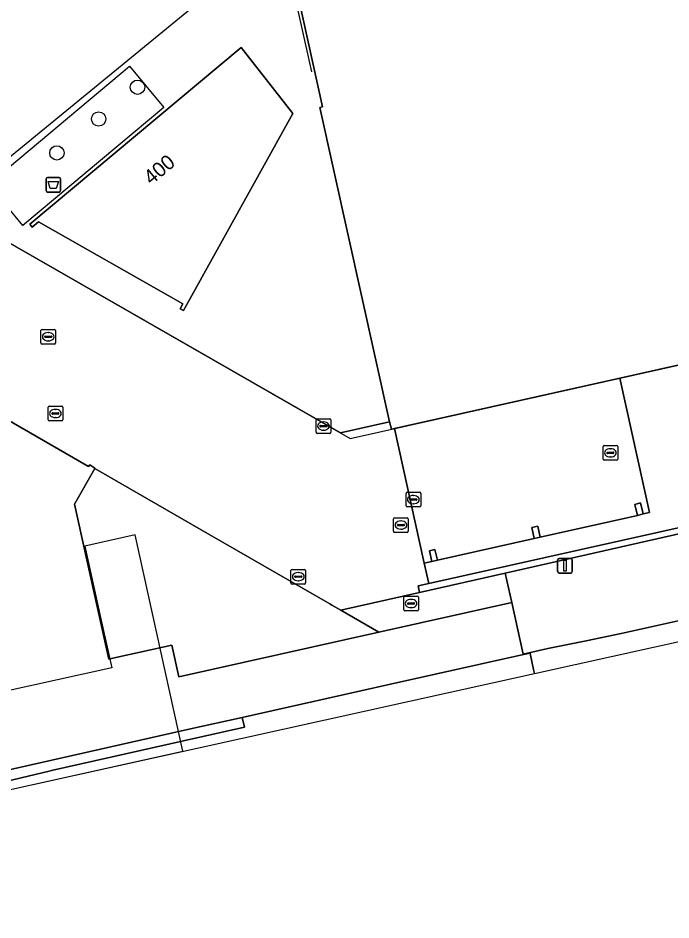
# Model space of a CAD drawing. Extents: x 160806 to 161707, y 383696 to 384148.
# Drawn here: x 161433.9 to 161478.4, y 383803.8 to 383865.4 of the extents above; entities that cross this region are included whole.
import ezdxf

# ---------------------------------------------------------------- set-up
doc = ezdxf.new("R2010")
doc.units = 0
for name, color, linetype in [('IMGEO_Afvalbak', 7, 'Continuous'), ('IMGEO_Boom', 7, 'Continuous'), ('IMGEO_Erf', 7, 'Continuous'), ('IMGEO_Groenvoorziening', 7, 'Continuous'), ('IMGEO_Hek', 7, 'Continuous'), ('IMGEO_Kolk', 7, 'Continuous'), ('IMGEO_Lichtmast', 7, 'Continuous'), ('IMGEO_Lijnafwatering', 7, 'Continuous'), ('IMGEO_Pand', 7, 'Continuous'), ('IMGEO_Pand_nummerreeks', 7, 'Continuous'), ('IMGEO_Pand_overbouw', 7, 'Continuous'), ('IMGEO_Pand_vergunning_verleend', 7, 'Continuous'), ('IMGEO_Rijbaan_lokaal_gesloten', 7, 'Continuous'), ('IMGEO_Rijbaan_lokaal_open', 7, 'Continuous'), ('IMGEO_Rioolput', 7, 'Continuous'), ('IMGEO_Spoorbaan_halfverhard', 7, 'Continuous'), ('IMGEO_Terreindeel_gesloten', 7, 'Continuous'), ('IMGEO_Verkeerseiland_open', 7, 'Continuous'), ('IMGEO_Voetgangersgebied_open', 7, 'Continuous'), ('IMGEO_Voetpad_open', 7, 'Continuous')]:
    doc.layers.add(name, color=color, linetype=linetype)

msp = doc.modelspace()

# ---------------------------------------------------------------- linework, layer by layer
at = {"layer": 'IMGEO_Afvalbak'}
for p, q in [((161435.802, 383853.602), (161435.802, 383854.402)), ((161435.802, 383854.402), (161435.802, 383853.602)), ((161435.902, 383854.502), (161436.692, 383854.502)), ((161436.692, 383854.502), (161435.902, 383854.502)), ((161436.792, 383854.402), (161436.792, 383853.602)), ((161436.792, 383853.602), (161436.792, 383854.402)), ((161436.692, 383853.502), (161435.902, 383853.502)), ((161435.902, 383853.502), (161436.692, 383853.502))]:
    msp.add_line(p, q, dxfattribs=at)
msp.add_lwpolyline([(161435.945, 383854.216), (161436.649, 383854.216), (161436.5, 383853.746), (161436.094, 383853.746), (161435.945, 383854.216)], dxfattribs=at)
for centre, start, end in [((161435.902, 383854.402), 90, 180), ((161435.902, 383854.402), 90, 180), ((161436.692, 383854.402), 0, 90), ((161436.692, 383854.402), 360, 90), ((161435.902, 383853.602), 180, 270), ((161435.902, 383853.602), 180, 270), ((161436.692, 383853.602), 270, 0), ((161436.692, 383853.602), 270, 0)]:
    msp.add_arc(centre, 0.1, start, end, dxfattribs=at)
at = {"layer": 'IMGEO_Boom'}
for centre in [(161442.039, 383860.652), (161439.388, 383858.484), (161436.538, 383856.171)]:
    msp.add_circle(centre, 0.489, dxfattribs=at)
at = {"layer": 'IMGEO_Erf'}
msp.add_lwpolyline([(161439.133, 383834.644), (161437.743, 383832.2), (161440.079, 383821.637), (161440.151, 383821.653), (161444.389, 383822.588), (161444.86, 383820.431), (161458.497, 383823.475), (161455.916, 383824.962), (161455.299, 383825.318), (161455.145, 383825.407), (161446.976, 383830.114)], close=True, dxfattribs=at)
at = {"layer": 'IMGEO_Groenvoorziening'}
msp.add_lwpolyline([(161573.981, 383851.379), (161498.641, 383834.626), (161467.119, 383827.496), (161467.565, 383825.499), (161468.352, 383821.972), (161470.021, 383822.345), (161472.634, 383822.879), (161475.023, 383823.371), (161479.934, 383824.467), (161509.272, 383830.942), (161514.217, 383832.035), (161521.635, 383833.723), (161580.201, 383846.689)], dxfattribs=at)
at = {"layer": 'IMGEO_Hek'}
for points in [[(161468.352, 383821.972), (161470.021, 383822.345), (161472.634, 383822.879), (161475.023, 383823.371), (161479.934, 383824.467), (161509.272, 383830.942), (161514.217, 383832.035), (161521.635, 383833.723), (161580.201, 383846.689), (161582.51, 383847.687), (161585.012, 383847.75), (161614.342, 383854.325), (161641.301, 383860.274), (161651.06, 383862.411), (161662.497, 383864.892), (161670.593, 383866.669), (161682.93, 383869.376), (161687.731, 383870.454), (161692.46, 383871.911), (161696.167, 383872.737)], [(161439.133, 383834.644), (161446.976, 383830.114), (161455.145, 383825.407)], [(161455.145, 383825.407), (161455.299, 383825.318)], [(161455.299, 383825.318), (161455.916, 383824.962)], [(161455.916, 383824.962), (161458.497, 383823.475)], [(161468.36, 383821.937), (161459.292, 383819.913), (161449.186, 383817.657)], [(161449.186, 383817.657), (161445.655, 383816.869), (161421.996, 383811.526)]]:
    msp.add_lwpolyline(points, dxfattribs=at)
at = {"layer": 'IMGEO_Kolk'}
for p, q in [((161454.221, 383837.106), (161454.221, 383837.958)), ((161454.296, 383838.032), (161455.148, 383838.032)), ((161454.709, 383837.812), (161454.734, 383837.812)), ((161455.222, 383837.958), (161455.222, 383837.106)), ((161454.48, 383837.526), (161454.48, 383837.538)), ((161454.918, 383837.489), (161454.52, 383837.489)), ((161454.523, 383837.575), (161454.921, 383837.575)), ((161454.732, 383837.252), (161454.707, 383837.252)), ((161454.964, 383837.538), (161454.964, 383837.526)), ((161455.148, 383837.032), (161454.296, 383837.032)), ((161452.506, 383826.829), (161452.506, 383827.681)), ((161452.581, 383827.755), (161453.433, 383827.755)), ((161452.808, 383827.298), (161453.206, 383827.298)), ((161452.994, 383827.535), (161453.019, 383827.535)), ((161453.507, 383827.681), (161453.507, 383826.829)), ((161453.433, 383826.755), (161452.581, 383826.755)), ((161452.765, 383827.249), (161452.765, 383827.261)), ((161453.203, 383827.212), (161452.805, 383827.212)), ((161453.017, 383826.975), (161452.992, 383826.975)), ((161453.249, 383827.261), (161453.249, 383827.249))]:
    msp.add_line(p, q, dxfattribs=at)
for points in [[(161454.221, 383837.106), (161454.221, 383837.958)], [(161454.296, 383838.032), (161455.148, 383838.032)], [(161455.222, 383837.958), (161455.222, 383837.106)], [(161455.148, 383837.032), (161454.296, 383837.032)], [(161452.506, 383826.829), (161452.506, 383827.681)], [(161452.581, 383827.755), (161453.433, 383827.755)], [(161453.507, 383827.681), (161453.507, 383826.829)], [(161453.433, 383826.755), (161452.581, 383826.755)]]:
    msp.add_lwpolyline(points, dxfattribs=at)
for centre, radius, start, end in [((161454.298, 383837.956), 0.0765, 91.55205, 178.44795), ((161454.298, 383837.956), 0.0765, 91.55205, 178.44795), ((161455.146, 383837.956), 0.0765, 1.55205, 88.44795), ((161455.146, 383837.956), 0.0765, 1.55205, 88.44795), ((161454.52, 383837.535), 0.0403, 85.87752, 175.75265), ((161454.517, 383837.525), 0.0366, 178.93798, 274.71019), ((161454.921, 383837.532), 0.043, 264.86636, 352.45326), ((161454.925, 383837.537), 0.0386, 1.73085, 96.63898), ((161454.298, 383837.108), 0.0765, 181.55205, 268.44795), ((161454.298, 383837.108), 0.0765, 181.55205, 268.44795), ((161455.146, 383837.108), 0.0765, 271.55205, 358.44795), ((161455.146, 383837.108), 0.0765, 271.55205, 358.44795), ((161452.583, 383827.679), 0.0765, 91.55205, 178.44795), ((161452.583, 383827.679), 0.0765, 91.55205, 178.44795), ((161452.805, 383827.258), 0.0403, 85.87752, 175.75265), ((161453.21, 383827.26), 0.0386, 1.73085, 96.63898), ((161453.431, 383827.679), 0.0765, 1.55205, 88.44795), ((161453.431, 383827.679), 0.0765, 1.55205, 88.44795), ((161452.583, 383826.831), 0.0765, 181.55205, 268.44795), ((161452.583, 383826.831), 0.0765, 181.55205, 268.44795), ((161452.802, 383827.248), 0.0366, 178.93798, 274.71019), ((161453.206, 383827.255), 0.043, 264.86636, 352.45326), ((161453.431, 383826.831), 0.0765, 271.55205, 358.44795), ((161453.431, 383826.831), 0.0765, 271.55205, 358.44795)]:
    msp.add_arc(centre, radius, start, end, dxfattribs=at)
for centre, major_axis, ratio, start_param, end_param in [((161454.708, 383837.532), (-0.387, 0.002), 0.722429, 4.712389, 7.853982), ((161454.733, 383837.532), (-0.39, 0.002), 0.717154, 1.570796, 4.712389), ((161452.993, 383827.255), (-0.387, 0.002), 0.722429, 4.712389, 7.853982), ((161453.018, 383827.255), (-0.39, 0.002), 0.717154, 1.570796, 4.712389)]:
    msp.add_ellipse(centre, major_axis=major_axis, ratio=ratio, start_param=start_param, end_param=end_param, dxfattribs=at)
at = {"layer": 'IMGEO_Lichtmast'}
for p, q in [((161470.693, 383827.601), (161470.693, 383828.401)), ((161470.693, 383828.401), (161470.693, 383827.601)), ((161470.793, 383828.501), (161471.583, 383828.501)), ((161471.583, 383828.501), (161470.793, 383828.501)), ((161471.683, 383828.401), (161471.683, 383827.601)), ((161471.683, 383827.601), (161471.683, 383828.401)), ((161471.583, 383827.501), (161470.793, 383827.501)), ((161470.793, 383827.501), (161471.583, 383827.501))]:
    msp.add_line(p, q, dxfattribs=at)
msp.add_lwpolyline([(161471.113, 383828.376), (161471.263, 383828.376), (161471.263, 383827.626), (161471.113, 383827.626), (161471.113, 383828.376)], dxfattribs=at)
for centre, start, end in [((161470.793, 383828.401), 90, 180), ((161470.793, 383828.401), 90, 180), ((161471.583, 383828.401), 0, 90), ((161471.583, 383828.401), 360, 90), ((161470.793, 383827.601), 180, 270), ((161470.793, 383827.601), 180, 270), ((161471.583, 383827.601), 270, 0), ((161471.583, 383827.601), 270, 0)]:
    msp.add_arc(centre, 0.1, start, end, dxfattribs=at)
at = {"layer": 'IMGEO_Lijnafwatering'}
for points in [[(161451.826, 383870.993), (161453.9, 383861.703)], [(161446.281, 383866.489), (161429.508, 383852.763)]]:
    msp.add_lwpolyline(points, dxfattribs=at)
at = {"layer": 'IMGEO_Pand'}
for points in [[(161468.392, 383879.273), (161466.655, 383877.86), (161465.897, 383881.096), (161452.306, 383869.965), (161454.649, 383859.314), (161454.467, 383859.266), (161459.23, 383837.816), (161459.371, 383837.315), (161459.571, 383837.36), (161474.936, 383840.799), (161489.445, 383844.046), (161504.78, 383847.479), (161501.103, 383863.975), (161500.733, 383865.636), (161500.564, 383866.393), (161496.865, 383882.93), (161496.125, 383886.224), (161492.387, 383902.807), (161472.218, 383886.284), (161472.911, 383882.95), (161471.213, 383881.568)], [(161421.996, 383811.526), (161445.655, 383816.869), (161449.186, 383817.657), (161459.292, 383819.913), (161468.36, 383821.937), (161468.352, 383821.972), (161467.565, 383825.499), (161458.497, 383823.475), (161444.86, 383820.431), (161444.389, 383822.588), (161440.151, 383821.653), (161440.079, 383821.637), (161437.743, 383832.2), (161439.133, 383834.644), (161439.136, 383834.65), (161438.779, 383834.879), (161438.695, 383834.766), (161432.999, 383838.061)]]:
    msp.add_lwpolyline(points, dxfattribs=at)
for points in [[(161445.128, 383845.88), (161444.948, 383845.529), (161445.17, 383845.408), (161452.644, 383858.861), (161449.115, 383863.351), (161434.699, 383851.304), (161434.859, 383851.112), (161435.296, 383851.477)], [(161476.347, 383832.284), (161475.96, 383832.191), (161476.142, 383831.439), (161476.528, 383831.533)], [(161469.353, 383830.703), (161468.944, 383830.62), (161469.095, 383829.871), (161469.504, 383829.954)], [(161462.322, 383829.103), (161461.943, 383829.01), (161462.119, 383828.288), (161462.499, 383828.381)]]:
    msp.add_lwpolyline(points, close=True, dxfattribs=at)
at = {"layer": 'IMGEO_Pand_overbouw'}
for points in [[(161576.544, 383863.524), (161556.299, 383953.974), (161403.923, 383918.874), (161417.58, 383859.039), (161456.542, 383836.683)], [(161476.142, 383831.439), (161475.96, 383832.191), (161476.347, 383832.284), (161476.528, 383831.533), (161476.962, 383831.641), (161474.936, 383840.799), (161459.571, 383837.36), (161461.599, 383828.173), (161462.119, 383828.288), (161461.943, 383829.01), (161462.322, 383829.103), (161462.499, 383828.381), (161469.095, 383829.871), (161468.944, 383830.62), (161469.353, 383830.703), (161469.504, 383829.954)], [(161445.142, 383815.339), (161441.873, 383830.1), (161438.438, 383829.334), (161439.521, 383824.478), (161440.29, 383821.029), (161419.78, 383816.517), (161421.083, 383810.599), (161402.46, 383805.86), (161402.903, 383803.833), (161432.009, 383812.432)]]:
    msp.add_lwpolyline(points, close=True, dxfattribs=at)
at = {"layer": 'IMGEO_Pand_vergunning_verleend'}
msp.add_lwpolyline([(161431.877, 383854.037), (161441.49, 383862.083), (161443.842, 383859.273), (161434.229, 383851.226)], close=True, dxfattribs=at)
at = {"layer": 'IMGEO_Rijbaan_lokaal_gesloten'}
msp.add_lwpolyline([(161489.445, 383844.046), (161474.936, 383840.799), (161476.962, 383831.641), (161476.528, 383831.533), (161476.142, 383831.439), (161469.504, 383829.954), (161469.095, 383829.871), (161462.499, 383828.381), (161462.119, 383828.288), (161461.599, 383828.173), (161461.912, 383826.794), (161498.576, 383834.978)], dxfattribs=at)
at = {"layer": 'IMGEO_Rijbaan_lokaal_open'}
msp.add_lwpolyline([(161432.999, 383838.061), (161438.695, 383834.766), (161438.779, 383834.879), (161439.136, 383834.65), (161439.133, 383834.644), (161446.976, 383830.114), (161455.145, 383825.407), (161455.299, 383825.318), (161455.916, 383824.962), (161461.28, 383826.175), (161461.178, 383826.63), (161461.912, 383826.794), (161461.599, 383828.173), (161459.571, 383837.36), (161459.371, 383837.315), (161459.23, 383837.816), (161455.886, 383837.059), (161417.58, 383859.039)], dxfattribs=at)
msp.add_lwpolyline([(161474.936, 383840.799), (161459.571, 383837.36), (161461.599, 383828.173), (161462.119, 383828.288), (161461.943, 383829.01), (161462.322, 383829.103), (161462.499, 383828.381), (161469.095, 383829.871), (161468.944, 383830.62), (161469.353, 383830.703), (161469.504, 383829.954), (161476.142, 383831.439), (161475.96, 383832.191), (161476.347, 383832.284), (161476.528, 383831.533), (161476.962, 383831.641)], close=True, dxfattribs=at)
at = {"layer": 'IMGEO_Rioolput'}
for p, q in [((161435.451, 383843.201), (161435.451, 383844.053)), ((161435.526, 383844.127), (161436.378, 383844.127)), ((161435.939, 383843.907), (161435.964, 383843.907)), ((161436.452, 383844.053), (161436.452, 383843.201)), ((161435.71, 383843.621), (161435.71, 383843.633)), ((161436.148, 383843.584), (161435.75, 383843.584)), ((161435.753, 383843.67), (161436.151, 383843.67)), ((161435.962, 383843.347), (161435.937, 383843.347)), ((161436.194, 383843.633), (161436.194, 383843.621)), ((161436.378, 383843.127), (161435.526, 383843.127)), ((161435.941, 383837.966), (161435.941, 383838.818)), ((161436.016, 383838.892), (161436.868, 383838.892)), ((161436.2, 383838.386), (161436.2, 383838.398)), ((161436.243, 383838.435), (161436.641, 383838.435)), ((161436.429, 383838.672), (161436.454, 383838.672)), ((161436.684, 383838.398), (161436.684, 383838.386)), ((161436.942, 383838.818), (161436.942, 383837.966)), ((161436.868, 383837.892), (161436.016, 383837.892)), ((161436.638, 383838.349), (161436.24, 383838.349)), ((161436.452, 383838.112), (161436.427, 383838.112)), ((161473.791, 383835.279), (161473.791, 383836.131)), ((161473.866, 383836.205), (161474.718, 383836.205)), ((161474.279, 383835.985), (161474.304, 383835.985)), ((161474.792, 383836.131), (161474.792, 383835.279)), ((161474.05, 383835.699), (161474.05, 383835.711)), ((161474.488, 383835.662), (161474.09, 383835.662)), ((161474.093, 383835.748), (161474.491, 383835.748)), ((161474.302, 383835.425), (161474.277, 383835.425)), ((161474.534, 383835.711), (161474.534, 383835.699)), ((161474.718, 383835.205), (161473.866, 383835.205)), ((161460.351, 383832.087), (161460.351, 383832.939)), ((161460.426, 383833.013), (161461.278, 383833.013)), ((161461.352, 383832.939), (161461.352, 383832.087)), ((161460.61, 383832.507), (161460.61, 383832.519)), ((161461.048, 383832.47), (161460.65, 383832.47)), ((161460.653, 383832.556), (161461.051, 383832.556)), ((161460.862, 383832.233), (161460.837, 383832.233)), ((161460.839, 383832.793), (161460.864, 383832.793)), ((161461.094, 383832.519), (161461.094, 383832.507)), ((161461.278, 383832.013), (161460.426, 383832.013)), ((161459.508, 383830.353), (161459.508, 383831.205)), ((161459.583, 383831.279), (161460.435, 383831.279)), ((161459.996, 383831.059), (161460.021, 383831.059)), ((161460.509, 383831.205), (161460.509, 383830.353)), ((161459.767, 383830.773), (161459.767, 383830.785)), ((161460.205, 383830.736), (161459.807, 383830.736)), ((161459.81, 383830.822), (161460.208, 383830.822)), ((161460.019, 383830.499), (161459.994, 383830.499)), ((161460.251, 383830.785), (161460.251, 383830.773)), ((161460.435, 383830.279), (161459.583, 383830.279)), ((161460.196, 383824.999), (161460.196, 383825.851)), ((161460.271, 383825.925), (161461.123, 383825.925)), ((161460.498, 383825.468), (161460.896, 383825.468)), ((161460.684, 383825.705), (161460.709, 383825.705)), ((161461.197, 383825.851), (161461.197, 383824.999)), ((161461.123, 383824.925), (161460.271, 383824.925)), ((161460.455, 383825.419), (161460.455, 383825.431)), ((161460.893, 383825.382), (161460.495, 383825.382)), ((161460.707, 383825.145), (161460.682, 383825.145)), ((161460.939, 383825.431), (161460.939, 383825.419))]:
    msp.add_line(p, q, dxfattribs=at)
for points in [[(161435.451, 383843.201), (161435.451, 383844.053)], [(161435.526, 383844.127), (161436.378, 383844.127)], [(161436.452, 383844.053), (161436.452, 383843.201)], [(161436.378, 383843.127), (161435.526, 383843.127)], [(161435.941, 383837.966), (161435.941, 383838.818)], [(161436.016, 383838.892), (161436.868, 383838.892)], [(161436.942, 383838.818), (161436.942, 383837.966)], [(161436.868, 383837.892), (161436.016, 383837.892)], [(161473.791, 383835.279), (161473.791, 383836.131)], [(161473.866, 383836.205), (161474.718, 383836.205)], [(161474.792, 383836.131), (161474.792, 383835.279)], [(161474.718, 383835.205), (161473.866, 383835.205)], [(161460.351, 383832.087), (161460.351, 383832.939)], [(161460.426, 383833.013), (161461.278, 383833.013)], [(161461.352, 383832.939), (161461.352, 383832.087)], [(161461.278, 383832.013), (161460.426, 383832.013)], [(161459.508, 383830.353), (161459.508, 383831.205)], [(161459.583, 383831.279), (161460.435, 383831.279)], [(161460.509, 383831.205), (161460.509, 383830.353)], [(161460.435, 383830.279), (161459.583, 383830.279)], [(161460.196, 383824.999), (161460.196, 383825.851)], [(161460.271, 383825.925), (161461.123, 383825.925)], [(161461.197, 383825.851), (161461.197, 383824.999)], [(161461.123, 383824.925), (161460.271, 383824.925)]]:
    msp.add_lwpolyline(points, dxfattribs=at)
for centre, radius, start, end in [((161435.528, 383844.051), 0.0765, 91.55205, 178.44795), ((161435.528, 383844.051), 0.0765, 91.55205, 178.44795), ((161436.376, 383844.051), 0.0765, 1.55205, 88.44795), ((161436.376, 383844.051), 0.0765, 1.55205, 88.44795), ((161435.75, 383843.63), 0.0403, 85.87752, 175.75265), ((161435.747, 383843.62), 0.0366, 178.93798, 274.71019), ((161436.151, 383843.627), 0.043, 264.86636, 352.45326), ((161436.155, 383843.632), 0.0386, 1.73085, 96.63898), ((161435.528, 383843.203), 0.0765, 181.55205, 268.44795), ((161435.528, 383843.203), 0.0765, 181.55205, 268.44795), ((161436.376, 383843.203), 0.0765, 271.55205, 358.44795), ((161436.376, 383843.203), 0.0765, 271.55205, 358.44795), ((161436.018, 383838.816), 0.0765, 91.55205, 178.44795), ((161436.018, 383838.816), 0.0765, 91.55205, 178.44795), ((161436.24, 383838.395), 0.0403, 85.87752, 175.75265), ((161436.237, 383838.385), 0.0366, 178.93798, 274.71019), ((161436.641, 383838.392), 0.043, 264.86636, 352.45326), ((161436.645, 383838.397), 0.0386, 1.73085, 96.63898), ((161436.866, 383838.816), 0.0765, 1.55205, 88.44795), ((161436.866, 383838.816), 0.0765, 1.55205, 88.44795), ((161436.018, 383837.968), 0.0765, 181.55205, 268.44795), ((161436.018, 383837.968), 0.0765, 181.55205, 268.44795), ((161436.866, 383837.968), 0.0765, 271.55205, 358.44795), ((161436.866, 383837.968), 0.0765, 271.55205, 358.44795), ((161473.868, 383836.129), 0.0765, 91.55205, 178.44795), ((161473.868, 383836.129), 0.0765, 91.55205, 178.44795), ((161474.716, 383836.129), 0.0765, 1.55205, 88.44795), ((161474.716, 383836.129), 0.0765, 1.55205, 88.44795), ((161474.09, 383835.708), 0.0403, 85.87752, 175.75265), ((161474.087, 383835.698), 0.0366, 178.93798, 274.71019), ((161474.491, 383835.705), 0.043, 264.86636, 352.45326), ((161474.495, 383835.71), 0.0386, 1.73085, 96.63898), ((161473.868, 383835.281), 0.0765, 181.55205, 268.44795), ((161473.868, 383835.281), 0.0765, 181.55205, 268.44795), ((161474.716, 383835.281), 0.0765, 271.55205, 358.44795), ((161474.716, 383835.281), 0.0765, 271.55205, 358.44795), ((161460.428, 383832.937), 0.0765, 91.55205, 178.44795), ((161460.428, 383832.937), 0.0765, 91.55205, 178.44795), ((161461.276, 383832.937), 0.0765, 1.55205, 88.44795), ((161461.276, 383832.937), 0.0765, 1.55205, 88.44795), ((161460.65, 383832.516), 0.0403, 85.87752, 175.75265), ((161460.647, 383832.506), 0.0366, 178.93798, 274.71019), ((161461.051, 383832.513), 0.043, 264.86636, 352.45326), ((161461.055, 383832.518), 0.0386, 1.73085, 96.63898), ((161460.428, 383832.089), 0.0765, 181.55205, 268.44795), ((161460.428, 383832.089), 0.0765, 181.55205, 268.44795), ((161461.276, 383832.089), 0.0765, 271.55205, 358.44795), ((161461.276, 383832.089), 0.0765, 271.55205, 358.44795), ((161459.585, 383831.203), 0.0765, 91.55205, 178.44795), ((161459.585, 383831.203), 0.0765, 91.55205, 178.44795), ((161460.433, 383831.203), 0.0765, 1.55205, 88.44795), ((161460.433, 383831.203), 0.0765, 1.55205, 88.44795), ((161459.807, 383830.782), 0.0403, 85.87752, 175.75265), ((161459.804, 383830.772), 0.0366, 178.93798, 274.71019), ((161460.208, 383830.779), 0.043, 264.86636, 352.45326), ((161460.212, 383830.784), 0.0386, 1.73085, 96.63898), ((161459.585, 383830.355), 0.0765, 181.55205, 268.44795), ((161459.585, 383830.355), 0.0765, 181.55205, 268.44795), ((161460.433, 383830.355), 0.0765, 271.55205, 358.44795), ((161460.433, 383830.355), 0.0765, 271.55205, 358.44795), ((161460.273, 383825.849), 0.0765, 91.55205, 178.44795), ((161460.273, 383825.849), 0.0765, 91.55205, 178.44795), ((161460.495, 383825.428), 0.0403, 85.87752, 175.75265), ((161460.9, 383825.43), 0.0386, 1.73085, 96.63898), ((161461.121, 383825.849), 0.0765, 1.55205, 88.44795), ((161461.121, 383825.849), 0.0765, 1.55205, 88.44795), ((161460.273, 383825.001), 0.0765, 181.55205, 268.44795), ((161460.273, 383825.001), 0.0765, 181.55205, 268.44795), ((161460.492, 383825.418), 0.0366, 178.93798, 274.71019), ((161460.896, 383825.425), 0.043, 264.86636, 352.45326), ((161461.121, 383825.001), 0.0765, 271.55205, 358.44795), ((161461.121, 383825.001), 0.0765, 271.55205, 358.44795)]:
    msp.add_arc(centre, radius, start, end, dxfattribs=at)
for centre, major_axis, ratio, start_param, end_param in [((161435.938, 383843.627), (-0.387, 0.002), 0.722429, 4.712389, 7.853982), ((161435.963, 383843.627), (-0.39, 0.002), 0.717154, 1.570796, 4.712389), ((161436.428, 383838.392), (-0.387, 0.002), 0.722429, 4.712389, 7.853982), ((161436.453, 383838.392), (-0.39, 0.002), 0.717154, 1.570796, 4.712389), ((161474.278, 383835.705), (-0.387, 0.002), 0.722429, 4.712389, 7.853982), ((161474.303, 383835.705), (-0.39, 0.002), 0.717154, 1.570796, 4.712389), ((161460.838, 383832.513), (-0.387, 0.002), 0.722429, 4.712389, 7.853982), ((161460.863, 383832.513), (-0.39, 0.002), 0.717154, 1.570796, 4.712389), ((161459.995, 383830.779), (-0.387, 0.002), 0.722429, 4.712389, 7.853982), ((161460.02, 383830.779), (-0.39, 0.002), 0.717154, 1.570796, 4.712389), ((161460.683, 383825.425), (-0.387, 0.002), 0.722429, 4.712389, 7.853982), ((161460.708, 383825.425), (-0.39, 0.002), 0.717154, 1.570796, 4.712389)]:
    msp.add_ellipse(centre, major_axis=major_axis, ratio=ratio, start_param=start_param, end_param=end_param, dxfattribs=at)
at = {"layer": 'IMGEO_Spoorbaan_halfverhard'}
msp.add_lwpolyline([(161580.201, 383846.689), (161521.635, 383833.723), (161514.217, 383832.035), (161509.272, 383830.942), (161479.934, 383824.467), (161475.023, 383823.371), (161472.634, 383822.879), (161470.021, 383822.345), (161468.352, 383821.972), (161468.36, 383821.937), (161468.808, 383822.037), (161468.839, 383821.9), (161469.057, 383820.924), (161469.119, 383820.647), (161634.815, 383857.326)], dxfattribs=at)
at = {"layer": 'IMGEO_Terreindeel_gesloten'}
msp.add_lwpolyline([(161432.009, 383812.432), (161469.119, 383820.647), (161469.057, 383820.924), (161468.839, 383821.9), (161468.808, 383822.037), (161468.36, 383821.937), (161459.292, 383819.913), (161449.186, 383817.657), (161449.336, 383816.984), (161445.167, 383816.052), (161436.171, 383814.021), (161436.008, 383813.986), (161428.163, 383812.12)], dxfattribs=at)
msp.add_lwpolyline([(161407.286, 383806.741), (161407.377, 383806.449), (161409.582, 383807.115), (161414.161, 383808.436), (161416.224, 383809.026), (161422.312, 383810.624), (161428.163, 383812.12), (161436.008, 383813.986), (161436.171, 383814.021), (161445.167, 383816.052), (161449.336, 383816.984), (161449.186, 383817.657), (161445.655, 383816.869), (161421.996, 383811.526), (161422.148, 383810.834), (161421.845, 383810.767), (161421.083, 383810.599), (161407.187, 383807.061), (161402.822, 383805.951), (161402.977, 383805.44)], close=True, dxfattribs=at)
at = {"layer": 'IMGEO_Verkeerseiland_open'}
msp.add_lwpolyline([(161573.981, 383851.379), (161587.103, 383854.297), (161587.517, 383854.389), (161587.399, 383854.956), (161586.966, 383854.859), (161578.911, 383853.047), (161498.576, 383834.978), (161461.912, 383826.794), (161461.178, 383826.63), (161461.28, 383826.175), (161467.119, 383827.496), (161498.641, 383834.626)], close=True, dxfattribs=at)
at = {"layer": 'IMGEO_Voetgangersgebied_open'}
msp.add_lwpolyline([(161430.482, 383867.488), (161425.009, 383863.006), (161424.344, 383862.463), (161424.185, 383862.737), (161423.37, 383864.191), (161418.734, 383860.447), (161417.58, 383859.039), (161455.886, 383837.059), (161459.23, 383837.816), (161454.467, 383859.266), (161454.649, 383859.314), (161452.306, 383869.965)], dxfattribs=at)
msp.add_lwpolyline([(161445.17, 383845.408), (161444.948, 383845.529), (161445.128, 383845.88), (161435.296, 383851.477), (161434.859, 383851.112), (161434.699, 383851.304), (161449.115, 383863.351), (161452.644, 383858.861)], close=True, dxfattribs=at)
at = {"layer": 'IMGEO_Voetpad_open'}
msp.add_lwpolyline([(161467.119, 383827.496), (161461.28, 383826.175), (161455.916, 383824.962), (161458.497, 383823.475), (161467.565, 383825.499)], close=True, dxfattribs=at)

# ---------------------------------------------------------------- texts
at = {"layer": 'IMGEO_Pand_nummerreeks'}
msp.add_text('400', height=1, rotation=39.79702, dxfattribs=at).set_placement((161442.98, 383853.945))

doc.saveas('drawing.dxf')
